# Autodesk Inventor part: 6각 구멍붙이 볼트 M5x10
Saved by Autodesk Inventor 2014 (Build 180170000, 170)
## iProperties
Created: 2026-07
Part Number: 6각 구멍붙이 볼트 M5x10
Material: 강철, 연강
Document SubType Name: Modeling
Designer: dg
Density: 7.86 g/cm^3
Appearance: 강철
Mass: 3.41959 g
Surface Area: 4.31157 cm^2
Volume: 0.435062 cm^3
Author: jhkim
Description: 6각머리 태핑 나사
Creation Date: 2026-07-02
Sending System: Autodesk Inventor 2027
Preprocessor: ST-DEVELOPER v20.1
Author: dg
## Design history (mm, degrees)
node "6각 구멍붙이 볼트 M5x101"
body "Solid1"
node "기준1"
